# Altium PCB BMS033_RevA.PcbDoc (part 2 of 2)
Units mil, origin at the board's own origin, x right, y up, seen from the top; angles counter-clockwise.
Board outline 3000 x 3000 mil, 2 copper layers (Layer 1 - Top Layer, Layer 2 - Bottom Layer), stack 32 mil thick; 87 components, 36 nets, 183 pads, 163 vias.
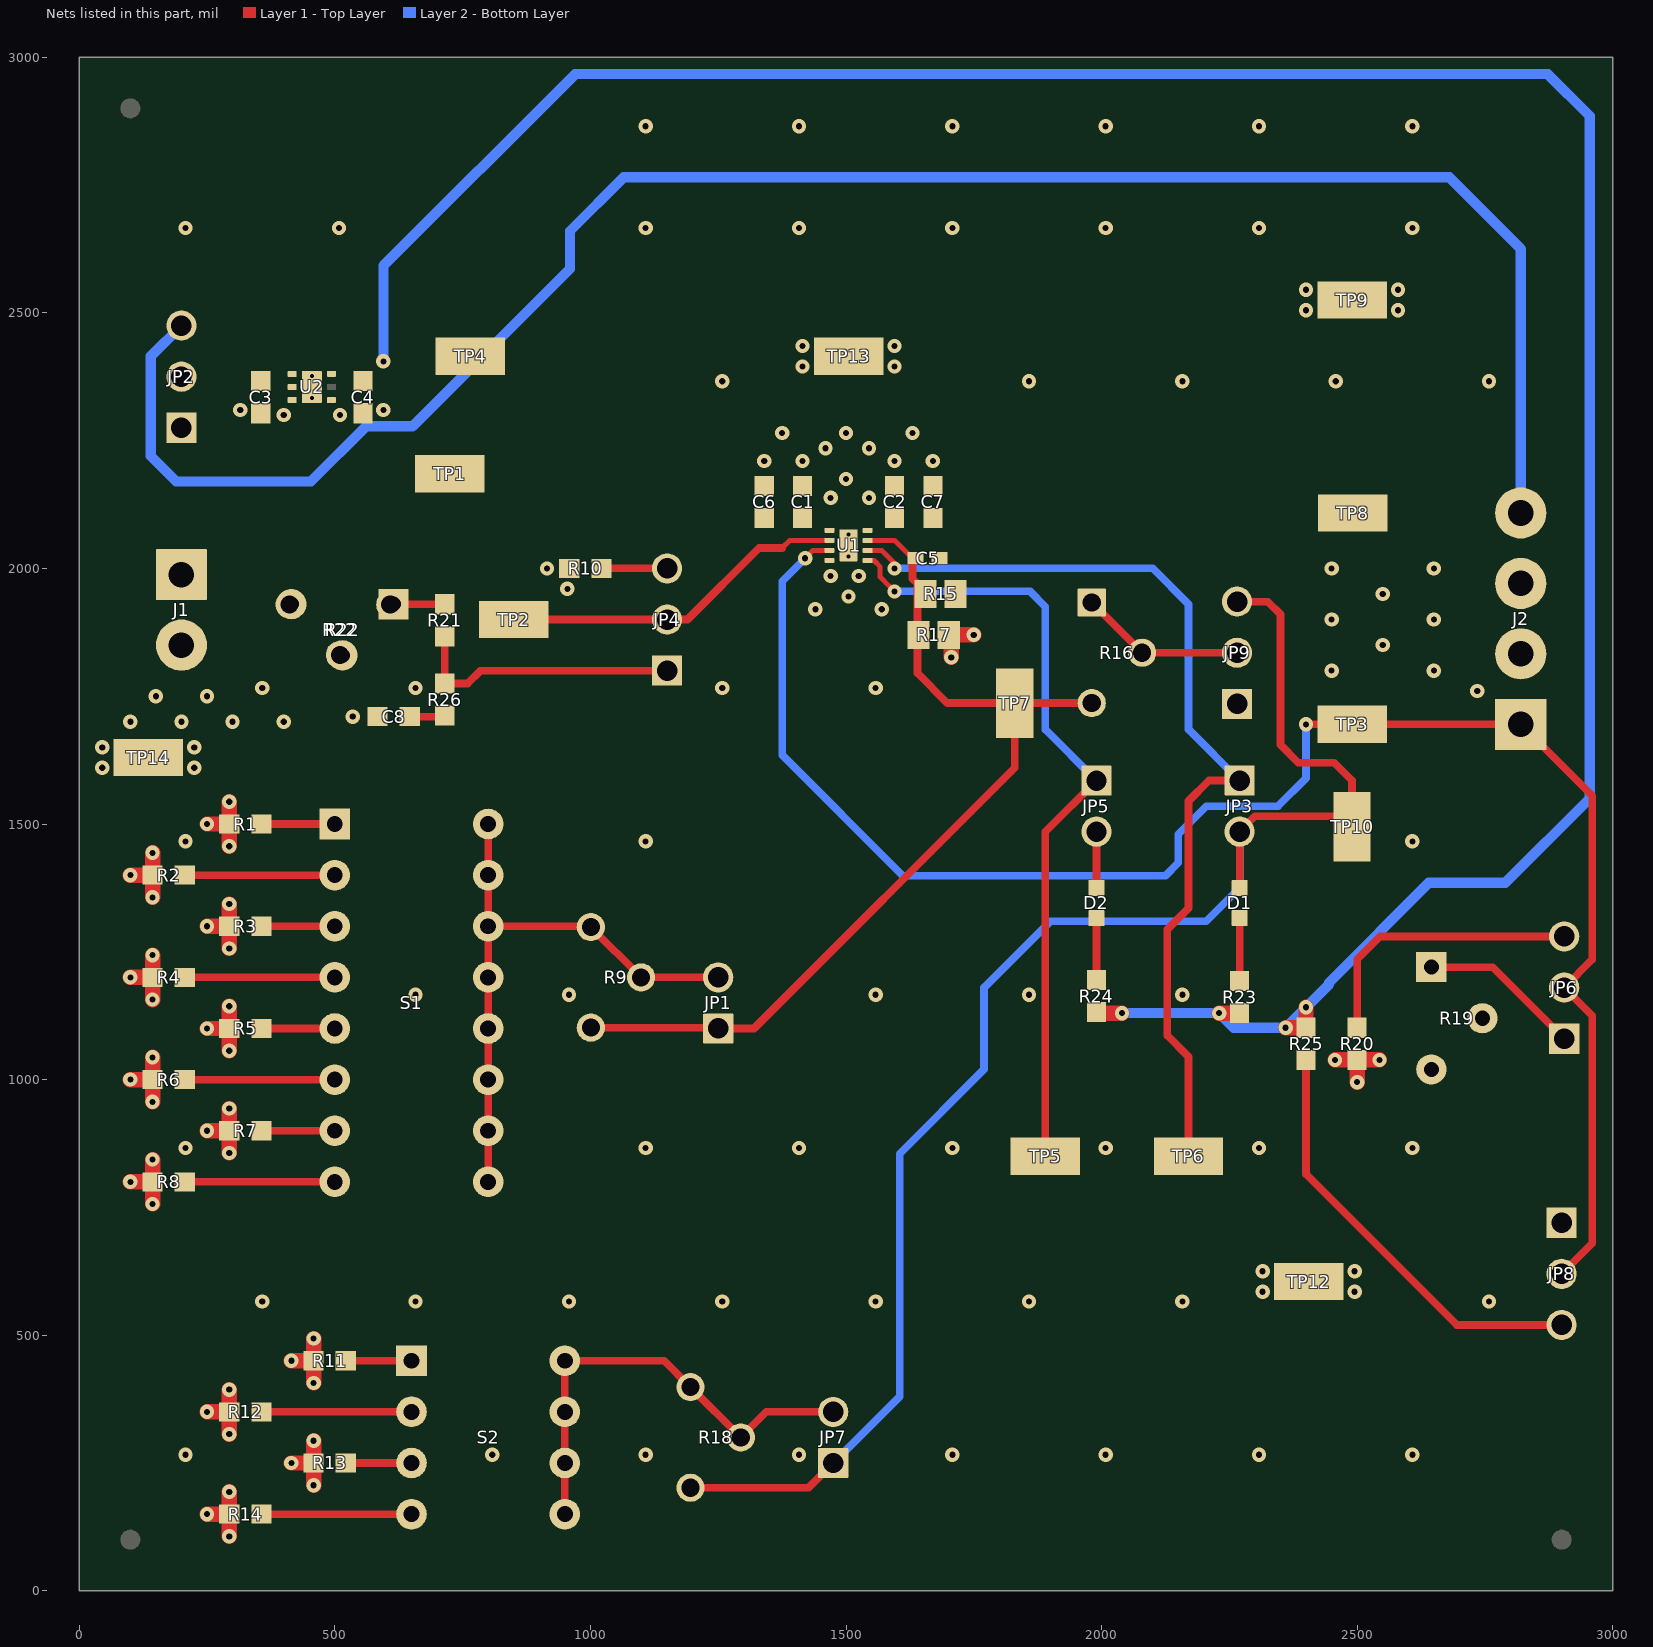
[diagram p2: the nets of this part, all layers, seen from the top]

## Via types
v1: diameter 28, hole 12, Layer 1 - Top Layer to Layer 2 - Bottom Layer, tented both sides, 159 vias
v2: diameter 19.68, hole 7.87, Layer 1 - Top Layer to Layer 2 - Bottom Layer, 4 vias

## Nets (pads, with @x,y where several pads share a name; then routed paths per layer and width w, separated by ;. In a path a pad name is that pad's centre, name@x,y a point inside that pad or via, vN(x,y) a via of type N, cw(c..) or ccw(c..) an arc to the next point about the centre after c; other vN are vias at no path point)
"/PG - TMR": D1.2 JP3.2 JP7.1 JP9.3 R18.3 TP10.1 | length 3002.3
  Layer 1 - Top Layer w15: R18.3@1195.79,201.57 1426.57,201.57 JP7.1@1475,250 ; JP9.3@2265,1935 2325,1935 2350,1910 2350,1655 2385,1620 2455,1620 2490,1585 TP10.1@2490,1495 2470,1515 2300,1515 JP3.2@2270,1485 D1.2@2270,1375
  Layer 2 - Bottom Layer w15: JP7.1@1475,250 1605,380 1605,855 1770,1020 1770,1180 1900,1310 2205,1310 2270,1375 JP3.2@2270,1485
Battery: C2.1 C5.1 C7.1 J2.4 JP2.3 R15.2 TP8.1 U1.8 | length 3845
  Layer 2 - Bottom Layer w20: JP2.3@200,2475 140,2415 140,2220 190,2170 453,2170 561.13,2278.13 652.1,2278.13 960,2586.03 960,2660 1065,2765 2680,2765 2820,2625 J2.4@2820,2108.39
GND: C1.2 C2.2 C3.2 C4.2 C6.2 C7.2 C8.1 J1.2 J2.2 J2.3 JP8.1 JP9.1 R1.1 R2.1 R3.1 R4.1 R5.1 R6.1 R7.1 R8.1 R10.2 R11.1 R12.1 R13.1 R14.1 R17.1 R19.2 R19.3 R20.1 R22.2 R22.3 TP9.1 TP12.1 TP13.1 TP14.1 U1.4 U1.9@1505,2045 U2.3 U2.4 U2.7@455,2355 | length 1790.7
  Layer 1 - Top Layer w30: v1(100,800) R8.1@143.5,800 ; v1(100,1000) R6.1@143.5,1000 ; v1(100,1200) R4.1@143.5,1200 ; v1(100,1400) R2.1@143.5,1400 ; v1(143.5,756.5) R8.1@143.5,800 ; v1(143.5,843.5) R8.1@143.5,800 ; v1(143.5,956.5) R6.1@143.5,1000 ; v1(143.5,1043.5) R6.1@143.5,1000 ; v1(143.5,1156.5) R4.1@143.5,1200 ; v1(143.5,1243.5) R4.1@143.5,1200 ; v1(143.5,1356.5) R2.1@143.5,1400 ; v1(143.5,1443.5) R2.1@143.5,1400 ; v1(250,150) R14.1@293.5,150 ; v1(250,350) R12.1@293.5,350 ; v1(250,900) R7.1@293.5,900 ; v1(250,1100) R5.1@293.5,1100 ; v1(250,1300) R3.1@293.5,1300 ; v1(250,1500) R1.1@293.5,1500 ; v1(293.5,106.5) R14.1@293.5,150 ; v1(293.5,193.5) R14.1@293.5,150 ; v1(293.5,306.5) R12.1@293.5,350 ; v1(293.5,393.5) R12.1@293.5,350 ; v1(293.5,856.5) R7.1@293.5,900 ; v1(293.5,943.5) R7.1@293.5,900 ; v1(293.5,1056.5) R5.1@293.5,1100 ; v1(293.5,1143.5) R5.1@293.5,1100 ; v1(293.5,1256.5) R3.1@293.5,1300 ; v1(293.5,1343.5) R3.1@293.5,1300 ; v1(293.5,1456.5) R1.1@293.5,1500 ; v1(293.5,1543.5) R1.1@293.5,1500 ; v1(415,250) R13.1@458.5,250 ; v1(415,450) R11.1@458.5,450 ; v1(458.5,206.5) R13.1@458.5,250 ; v1(458.5,293.5) R13.1@458.5,250 ; v1(458.5,406.5) R11.1@458.5,450 ; v1(458.5,493.5) R11.1@458.5,450 ; R17.1@1702.99,1870 v1(1750,1870) ; v1(1705.94,1825.94) R17.1@1705.94,1872.95 ; v1(2456.5,1038.5) R20.1@2500,1038.5 ; v1(2500,995) R20.1@2500,1038.5 ; v1(2543.5,1038.5) R20.1@2500,1038.5
  other v1: 208,266 808,266 1108,266 1408,266 1708,266 2008,266 2308,266 2608,266 358,566 658,566 958,566 1258,566 1558,566 1858,566 2158,566 2758,566 2315,585 2495,585 2315,625 2495,625 208,866 1108,866 1408,866 1708,866 2008,866 2308,866 2608,866 658,1166 958,1166 1558,1166 1858,1166 2158,1166 208,1466 1108,1466 2608,1466 45,1610 225,1610 45,1650 225,1650 100,1700 200,1700 300,1700 400,1700 535,1710 150,1750 250,1750 2735,1760 358,1766 658,1766 1258,1766 1558,1766 2450,1800 2650,1800 2550,1850 2450,1900 2650,1900 1440,1920 1570,1920 1505,1945 2550,1950 955,1960 1470,1985 1525,1985 915,2000 2450,2000 2650,2000 1470,2138 1545,2138 1500,2175 1340,2210 1415,2210 1595,2210 1670,2210 1460,2235 1545,2235 1375,2265 1500,2265 1630,2265 400,2300 510,2300 315,2310 595,2310 1258,2366 1858,2366 2158,2366 2458,2366 2758,2366 1415,2395 1595,2395 1415,2435 1595,2435 2400,2505 2580,2505 2400,2545 2580,2545 208,2666 508,2666 1108,2666 1408,2666 1708,2666 2008,2666 2308,2666 2608,2666 1108,2865 1408,2865 1708,2865 2008,2865 2308,2865 2608,2865
  other v2: 1505,2023.35 1505,2066.65 455,2333.35 455,2376.65
NetC1_1: C1.1 C6.1 J1.1 JP2.1 TP1.1 U1.1
NetC3_1: C3.1 JP2.2 U2.1 U2.2
NetC8_2: C8.2 R26.2 | length 69.3
  Layer 1 - Top Layer w15: C8.2@646.5,1710 712.99,1710 R26.2@715,1712.01
NetD1_1: D1.1 R23.1 | length 122.9
  Layer 1 - Top Layer w15: R23.1@2270,1193.03 D1.1@2270,1315.95
NetD2_1: D2.1 R24.1 | length 120.9
  Layer 1 - Top Layer w15: R24.1@1990,1195 D2.1@1990,1315.94
NetD2_2: D2.2 JP5.2 | length 132
  Layer 1 - Top Layer w15: D2.2@1990,1373.03 D2.2@1990,1375 JP5.2@1990,1485 JP5.2@1990,1505
NetJP1_2: JP1.2 R9.1 R9.2 S1.9 S1.10 S1.11 S1.12 S1.13 S1.14 S1.15 S1.16 | length 1191.4
  Layer 1 - Top Layer w15: S1.9@800,800 S1.10@800,900 S1.11@800,1000 S1.12@800,1100 S1.13@800,1200 S1.14@800,1300 ; S1.16@800,1500 S1.15@800,1400 S1.14@800,1300 ; JP1.2@1250,1200 R9.2@1099.21,1200 R9.1@1000.79,1298.43 999.21,1300 S1.14@800,1300
NetJP3_1: JP3.1 TP6.1 U1.6 | length 1909.3
  Layer 1 - Top Layer w10: U1.6@1542.4,2035.16 1569.84,2035.16 1595,2010 v1(1595,2000)
  Layer 1 - Top Layer w15: TP6.1@2170,850 2170,1045 2128.63,1086.37 2128.63,1293.63 2170,1335 2170,1545 2210,1585 JP3.1@2270,1585
  Layer 2 - Bottom Layer w15: v1(1595,2000) 2100,2000 2170,1930 2170,1685 JP3.1@2270,1585
NetJP4_1: JP4.1 R21.2 R26.1 | length 537.4
  Layer 1 - Top Layer w15: R21.2@715,1867.01 R26.1@715,1775 760,1775 785,1800 JP4.1@1150,1800
NetJP4_2: JP4.2 TP2.1 U1.2 | length 681.7
  Layer 1 - Top Layer w10: 1375,2040 1389.84,2054.84 U1.2@1467.6,2054.84
  Layer 1 - Top Layer w15: TP2.1@850,1900 JP4.2@1150,1900 1190,1900 1330,2040 1375,2040
NetJP4_3: JP4.3 R10.1 | length 128.5
  Layer 1 - Top Layer w15: R10.1@1021.5,2000 JP4.3@1150,2000
NetJP5_1: JP5.1 TP5.1 U1.5 | length 1568.8
  Layer 1 - Top Layer w10: U1.5@1542.4,2015.47 1554.53,2015.47 1566.87,2003.13 1566.87,1983.09 1584.74,1965.23 v1(1595,1955)
  Layer 1 - Top Layer w15: TP5.1@1890,850 1890,1485 JP5.1@1990,1585 JP5.1@2000,1595
  Layer 2 - Bottom Layer w15: v1(1595,1955) 1860,1955 1890,1925 1890,1685 JP5.1@1990,1585
NetJP6_1: JP6.1 R19.1 | length 318
  Layer 1 - Top Layer w15: R19.1@2645,1220 2765,1220 JP6.1@2905,1080
NetJP6_3: JP6.3 R20.2 | length 557.1
  Layer 1 - Top Layer w15: R20.2@2500,1101.5 2500,1235 2545,1280 JP6.3@2905,1280
NetJP7_2: JP7.2 R18.1 R18.2 S2.5 S2.6 S2.7 S2.8 | length 907.8
  Layer 1 - Top Layer w15: S2.5@950,150 S2.6@950,250 S2.7@950,350 S2.8@950,450 1144.21,450 R18.1@1195.79,398.43 R18.2@1294.21,300 1344.21,350 JP7.2@1475,350
NetJP8_3: JP8.3 R25.1 | length 845.7
  Layer 1 - Top Layer w15: R25.1@2400,1038.5 2400,815 2695,520 JP8.3@2900,520
NetJP9_2: JP9.2 R16.1 R16.2 | length 325
  Layer 1 - Top Layer w15: R16.1@1980.79,1933.43 R16.2@2079.21,1835 JP9.2@2265,1835
NetR1_2: R1.2 S1.1 | length 143.5
  Layer 1 - Top Layer w15: R1.2@356.5,1500 S1.1@500,1500
NetR2_2: R2.2 S1.2 | length 293.5
  Layer 1 - Top Layer w15: R2.2@206.5,1400 S1.2@500,1400
NetR3_2: R3.2 S1.3 | length 143.5
  Layer 1 - Top Layer w15: R3.2@356.5,1300 S1.3@500,1300
NetR4_2: R4.2 S1.4 | length 293.5
  Layer 1 - Top Layer w15: R4.2@206.5,1200 S1.4@500,1200
NetR5_2: R5.2 S1.5 | length 143.5
  Layer 1 - Top Layer w15: R5.2@356.5,1100 S1.5@500,1100
NetR6_2: R6.2 S1.6 | length 293.5
  Layer 1 - Top Layer w15: R6.2@206.5,1000 S1.6@500,1000
NetR7_2: R7.2 S1.7 | length 143.5
  Layer 1 - Top Layer w15: R7.2@356.5,900 S1.7@500,900
NetR8_2: R8.2 S1.8 | length 293.5
  Layer 1 - Top Layer w15: R8.2@206.5,800 S1.8@500,800
NetR11_2: R11.2 S2.1 | length 128.5
  Layer 1 - Top Layer w15: R11.2@521.5,450 S2.1@650,450
NetR12_2: R12.2 S2.2 | length 293.5
  Layer 1 - Top Layer w15: R12.2@356.5,350 S2.2@650,350
NetR13_2: R13.2 S2.3 | length 128.5
  Layer 1 - Top Layer w15: R13.2@521.5,250 S2.3@650,250
NetR14_2: R14.2 S2.4 | length 293.5
  Layer 1 - Top Layer w15: R14.2@356.5,150 S2.4@650,150
NetR21_1: R21.1 R22.1 | length 100
  Layer 1 - Top Layer w15: R22.1@615,1930 R21.1@715,1930
Pull-Up: C4.1 R23.2 R24.2 R25.2 TP4.1 U2.6 | length 5356.8
  Layer 1 - Top Layer w30: R24.2@1990,1132.01 1991.97,1130.04 v1(2040,1130.04) ; v1(2230,1130.04) R23.2@2270,1130.04 ; v1(2360,1101.5) R25.2@2400,1101.5 v1(2400,1141.5)
  Layer 2 - Bottom Layer w20: v1(595,2405) 595,2592 970,2967 2873,2967 2955,2885 2955,1550 2790,1385 2640,1385 2445,1190 2445,1186.5 v1(2400,1141.5) v1(2360,1101.5) 2258.54,1101.5 v1(2230,1130.04) v1(2040,1130.04)
"TS - /CE": J2.1 JP6.2 JP8.2 TP3.1 U1.3 | length 3420.6
  Layer 1 - Top Layer w10: v1(1420,2020) 1435.16,2035.16 U1.3@1467.6,2035.16
  Layer 1 - Top Layer w15: v1(2400,1695) TP3.1@2490,1695 J2.1@2820,1695 2960,1555 2960,1235 JP6.2@2905,1180 2960,1125 2960,680 JP8.2@2900,620
  Layer 2 - Bottom Layer w15: v1(1420,2020) 1375,1975 1375,1635 1611.03,1398.97 2125,1398.97 2150,1423.97 2150,1480 2205,1535 2345,1535 2400,1590 v1(2400,1695)
"VSET - FB": C5.2 JP1.1 R9.3 R15.1 R16.3 R17.2 TP7.1 U1.7 | length 1863.8
  Layer 1 - Top Layer w10: U1.7@1542.4,2054.84 1595.16,2054.84 C5.2@1630,2020
  Layer 1 - Top Layer w15: R9.3@1000.79,1101.57 1248.43,1101.57 JP1.1@1250,1100 1320,1100 1830,1610 TP7.1@1830,1736.57 ; C5.2@1630,2020 1630,1980 1640,1970 1640,1950 1640,1915 1640,1870 1640,1795 1698.43,1736.57 TP7.1@1830,1736.57 ; R16.3@1980.79,1736.57 TP7.1@1830,1736.57
pads on no net: FID1.1 FID2.1 FID3.1 H1.0 H2.0 H3.0 H4.0 LBL1.0 SH-JP1.0 SH-JP2.0 SH-JP3.0 SH-JP4.0 SH-JP5.0 SH-JP6.0 SH-JP7.0 SH-JP8.0 SH-JP9.0 U1.9@1505,2027.28 U1.9@1505,2062.72 U2.5 U2.7@455,2337.28 U2.7@455,2372.72

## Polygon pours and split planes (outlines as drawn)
GND on Layer 2 - Bottom Layer "Layer 2 - Bottom Layer - GND" (solid, remove dead copper, pour order 2): 20,20 2980,20 2980,2980 20,2980
GND on Layer 1 - Top Layer "Layer 1 - Top Layer - GND" (solid, remove dead copper, pour order 0): 20,20 2980,20 2980,2980 20,2980

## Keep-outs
Keep-Out Layer:
  text ".Layer_Name" at 577,-858.49 h60

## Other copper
Layer 1 - Top Layer:
  region net Battery: 1703.7,1910 1696.8,1916.9 1696.8,1978.2 1691.85,1983.15 1680,1995 1665,2010 1665,2035 1650,2050 1626,2050 1607,2069 1532,2069 1532,2082 1575,2125 1640,2125 1705,2125 1720,2140 1720,2190 1790,2260 1865,2260 2850,2260 2880,2230 2880,2080 2850,2050 1763,2050 1750,2037 1750,1918 1742,1910
  region net NetC1_1: 1440,2125 1310,2125 1295,2140 1295,2200 1235,2260 280,2260 230,2310 140,2310 100,2270 100,1970 140,1930 275,1930 414.5,2069.5 1476.5,2069.5 1478,2071 1478,2087
  region net NetC3_1: 421,2345 427,2351 427,2384 401,2410 175,2410 165,2400 165,2355 175,2345
  region net Pull-Up: 484,2375 486,2373 509,2373 536,2346 826,2346 845,2365 845,2450 825,2470 531,2470 484,2423
  region net GND: 1487,2105 1475.29,2116.71 1475.29,2135 1522.62,2135 1523,2009.99 1537.78,1995.22 1452.78,1995.22 1448.25,1999.75 1448.25,2016.25 1453,2021 1483,2021 1487,2025
  region net GND: 433,2336 435,2338 435,2427 451,2443 460,2443 462,2441 470.58,2441 475.48,2436.11 475.48,2342.52 479,2339 525,2339 533,2331 533,2322.17 405,2322 402,2325 402,2329 409,2336
  text ".Layer_Name" at 577,-858.49 h60
Layer 2 - Bottom Layer:
  pour cut-out: 1430.35,278.54 1430.35,349.74 1440,350 1440,278.54
  text ".Layer_Name" at 577,-858.49 h60

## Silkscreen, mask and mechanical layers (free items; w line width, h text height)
Top Overlay:
  lines w7: 272,2270 272,2305 ; 274,2356 274,2391 ; 277,2270 277,2305 ; 279,2356 279,2391 ; 282,2270 282,2305 ; 284,2356 284,2391 ; 287,2270 287,2305 ; 289,2356 289,2391 ; 291,2270 291,2305 ; 293,2356 293,2391 ; 297,2270 297,2305 ; 299,2356 299,2391 ; 1224,1881 1224,1916 ; 1224,1961 1224,1996 ; 1229,1881 1229,1916 ; 1229,1961 1229,1996 ; 1234,1881 1234,1916 ; 1234,1961 1234,1996 ; 1239,1881 1239,1916 ; 1239,1961 1239,1996 ; 1243,1881 1243,1916 ; 1243,1961 1243,1996 ; 1249,1881 1249,1916 ; 1249,1961 1249,1996 ; 1324,1081 1324,1116 ; 1324,1181 1324,1216 ; 1329,1081 1329,1116 ; 1329,1181 1329,1216 ; 1334,1081 1334,1116 ; 1334,1181 1334,1216 ; 1339,1081 1339,1116 ; 1339,1181 1339,1216 ; 1343,1081 1343,1116 ; 1343,1181 1343,1216 ; 1349,1081 1349,1116 ; 1349,1181 1349,1216 ; 1549,231 1549,266 ; 1549,331 1549,366 ; 1554,231 1554,266 ; 1554,331 1554,366 ; 1559,231 1559,266 ; 1559,331 1559,366 ; 1564,231 1564,266 ; 1564,331 1564,366 ; 1568,231 1568,266 ; 1568,331 1568,366 ; 1574,231 1574,266 ; 1574,331 1574,366 ; 1891,1469 1891,1504 ; 1891,1569 1891,1604 ; 1897,1469 1897,1504 ; 1897,1569 1897,1604 ; 1901,1469 1901,1504 ; 1901,1569 1901,1604 ; 1906,1469 1906,1504 ; 1906,1569 1906,1604 ; 1911,1469 1911,1504 ; 1911,1569 1911,1604 ; 1916,1469 1916,1504 ; 1916,1569 1916,1604 ; 2171,1469 2171,1504 ; 2171,1569 2171,1604 ; 2177,1469 2177,1504 ; 2177,1569 2177,1604 ; 2181,1469 2181,1504 ; 2181,1569 2181,1604 ; 2186,1469 2186,1504 ; 2186,1569 2186,1604 ; 2191,1469 2191,1504 ; 2191,1569 2191,1604 ; 2196,1469 2196,1504 ; 2196,1569 2196,1604 ; 2806,1164 2806,1199 ; 2806,1264 2806,1299 ; 2812,1164 2812,1199 ; 2812,1264 2812,1299 ; 2816,1164 2816,1199 ; 2816,1264 2816,1299 ; 2821,1164 2821,1199 ; 2821,1264 2821,1299 ; 2826,1164 2826,1199 ; 2826,1264 2826,1299 ; 2831,1164 2831,1199 ; 2831,1264 2831,1299 ; 267,2270 267,2305 302,2305 302,2270 267,2270 ; 269,2356 269,2391 304,2391 304,2356 269,2356 ; 1219,1881 1219,1916 1254,1916 1254,1881 1219,1881 ; 1219,1961 1254,1961 1254,1996 1219,1996 1219,1961 ; 1319,1081 1354,1081 1354,1116 1319,1116 1319,1081 ; 1319,1181 1354,1181 1354,1216 1319,1216 1319,1181 ; 1544,231 1579,231 1579,266 1544,266 1544,231 ; 1544,331 1579,331 1579,366 1544,366 1544,331 ; 1886,1469 1921,1469 1921,1504 1886,1504 1886,1469 ; 1886,1569 1921,1569 1921,1604 1886,1604 1886,1569 ; 2166,1469 2201,1469 2201,1504 2166,1504 2166,1469 ; 2166,1569 2201,1569 2201,1604 2166,1604 2166,1569 ; 2801,1164 2836,1164 2836,1199 2801,1199 2801,1164 ; 2801,1264 2836,1264 2836,1299 2801,1299 2801,1264
  text "OUT / (BAT)" at 109,2729 h70
  text "REG" at 139,2654 h70
  text "IN(+)" at 139,2554 h70
  text "OUT (Bat+)" at 2650,2435 h70
  text "GND" at 2420,2425 h75
  text "GND (Bat-)" at 2655,2364.18 h70
  text "GND" at 1435,2315 h75
  text "PULLUP" at 650,2310 h75
  text "GND" at 2750,2277.59 h70
  text "TS" at 2785,2203.39 h70
  text "/PG" at 2205,2144 h70
  text "VIN" at 670,2085 h75
  text "FB-GND" at 2143,2075 h70
  text "GND" at 2200,2008 h70
  text "BAT" at 2429,2005 h75
  text "ISET - ADJ" at 362,2003 h70
  text "FIXED" at 1266.56,1956.56 h70
  text "ISET" at 1265,1880 h70
  text "ISET" at 783,1805 h75
  text "ADJ" at 1215,1780 h70
  text "VSET-FB" at 1495,1685 h75
  text "TS-/CE" at 2385,1595 h75
  text "GND" at 65,1525 h75
  text "FIXED" at 2795,1490 h70
  text "TS" at 2863,1423.5 h70
  text "VSET-ADJ" at 903,1367 h70
  text "/PG-TMR" at 2418,1359 h75
  text "ADJ" at 2840,1353 h70
  text "STAT" at 1905,1235 h75
  text "PG" at 2230,1235 h75
  text "PG" at 2125,705 h75
  text "STAT" at 1805,690 h75
  text "GND" at 2335,500 h75
  text "TMR-ADJ" at 1105,470 h70
  text "ON" at 2854,402 h70
  text "/CE" at 2844,335.94 h70
  text "OFF" at 2838,270 h70
  text ".Layer_Name" at 577,-858.49 h60
Bottom Overlay:
  text ".Layer_Name" at 577,-858.49 h60
Top Paste:
  text ".Layer_Name" at 577,-858.49 h60
Bottom Paste:
  text ".Layer_Name" at 577,-858.49 h60
Top Solder:
  text ".Layer_Name" at 577,-858.49 h60
  text ".Layer_Name" at 577,-858.49 h60
Bottom Solder:
  text ".Layer_Name" at 577,-858.49 h60
Drill Guide:
  text ".Layer_Name" at 577,-858.49 h60
M1 Board Outline:
  the board outline again, w10
  text ".Layer_Name" at 577,-858.49 h60
M2 Board Dimensions:
  rectangle: 0,-275 125,-150
  rectangle: 125,-400 500,-275
  lines w7: 0,-275 1000,-275 ; 125,-400 125,-150 ; 250,-400 250,-150 ; 500,-400 500,-150 ; 750,-400 750,-150 ; 0,-400 1000,-400 1000,-150 0,-150 0,-400
  text ".Layer_Name" at 577,-858.49 h60
M3 3D STEP Top:
  text ".Layer_Name" at 577,-858.49 h60
M4 3D STEP Bottom:
  text ".Layer_Name" at 577,-858.49 h60
M5 Assembly Top:
  lines w10: -292,-930.17 6308,-930.17 ; -292,-726.83 6310,-726.83 ; -292,-523.5 -292,-1133.5 3713,-1133.5 6310,-1133.5 6310,-523.5 -291.5,-523.5 -291.5,-1133.5 1284,-1133.5 ; 2173,-1133.5 2173,-523.5 ; 3440,-726.83 3440,-523.5 ; 4280,-726.83 4280,-523.5 ; 4902,-1140 4902,-937.17
  text "COMPONENTS MARKED 'DNP' SHOULD NOT BE POPULATED." at 1153.5,-318.5 h60
  text "ASSEMBLY VARIANT:" at 1153,-434 h60
  text ".VariantName" at 2189,-434 h60
  text "PCB VIEWED FROM TOP SIDE" at -228.5,-655.67 h60
  text "BOARD #:" at 2248,-655.67 h60
  text ".PRJ_Number" at 2793.5,-655.67 h60
  text "REV:" at 3638,-655.67 h60
  text ".PCB_Rev" at 3929.5,-655.67 h60
  text "SVN REV:" at 4476,-655.67 h60
  text ".VersionControl_RevNumber" at 4982,-655.67 h60
  text "TID #:" at 2248,-859 h60
  text ".TID" at 2793.5,-859 h60
  text "PLOT NAME =" at -228.5,-1064.34 h60
  text ".plot_File_Name" at 577,-1064.34 h60
  text "GENERATED    :" at 2250,-1064.34 h60
  text ".Print_Date" at 3119.5,-1064.34 h60
  text ".Print_Time" at 3848.5,-1064.34 h60
  text "TEXAS INSTRUMENTS" at 5113,-1064.34 h60
M6 Assembly Bottom:
  lines w10: -292.5,-727.33 6309.5,-727.33 ; -290.5,-930.67 6309.5,-930.67 ; 1115.5,-1140.5 1115.5,-937.67 ; 1737.5,-727.33 1737.5,-524 ; 2577.5,-727.33 2577.5,-524 ; 3844.5,-1134 3844.5,-524 ; 4733.5,-1134 6309,-1134 6309,-524 -292.5,-524 -292.5,-1134 2304.5,-1134 6309.5,-1134 6309.5,-524
  text "COMPONENTS MARKED 'DNP' SHOULD NOT BE POPULATED." at 6102,-318 h60
  text ".VariantName" at 5058,-434 h60
  text "ASSEMBLY VARIANT:" at 6097,-434 h60
  text ".VersionControl_RevNumber" at 1035.5,-656.17 h60
  text "SVN REV:" at 1541.5,-656.17 h60
  text ".PCB_Rev" at 2088,-656.17 h60
  text "REV:" at 2379.5,-656.17 h60
  text ".PRJ_Number" at 3224,-656.17 h60
  text "BOARD #:" at 3769.5,-656.17 h60
  text "PCB VIEWED FROM BOTTOM SIDE" at 6246,-656.17 h60
  text ".TID" at 3224,-859.5 h60
  text "TID #:" at 3769.5,-859.5 h60
  text "TEXAS INSTRUMENTS" at 904.5,-1064.84 h60
  text ".Print_Time" at 2169,-1064.84 h60
  text ".Print_Date" at 2898,-1064.84 h60
  text "GENERATED    :" at 3767.5,-1064.84 h60
  text ".plot_File_Name" at 5440.5,-1064.84 h60
  text "PLOT NAME =" at 6246,-1064.84 h60
M9 Title Sheet:
  drawing of 1178 lines, arcs and shapes, not listed
  text "1" at 739.84,8036.5 h70
  text "2" at 3235.5,8036.5 h70
  text "3" at 5724.84,8036.5 h70
  text "4" at 8231.51,8036.5 h70
  text "5" at 10730.5,8036.5 h70
  text "6" at 13235.5,8036.5 h70
  text "A" at -416.5,6893.5 h70
  text "A" at 14383.5,6893.5 h70
  text "B" at -416.5,4513.5 h70
  text "B" at 14383.5,4513.5 h70
  text "C" at -416.5,2138.5 h70
  text "C" at 14383.5,2138.5 h70
  text "PROJECT TITLE:" at 11343.5,277.5 h45
  text ".PRJ_Title" at 11393.5,144.17 h70
  text "DESIGNED FOR:" at 11343.5,-23.5 h45
  text ".PRJ_Customer" at 11393.5,-163.5 h70
  text "D" at -416.5,-231.5 h70
  text "D" at 14383.5,-231.5 h70
  text "FILE NAME:" at 11343.5,-323.5 h45
  text ".PCB_File_Name_No_Path" at 11393.5,-443.5 h70
  text "Texas Instruments (TI) and/or its licensors do not warrant the accuracy or completeness of this specification" at 6374,-605.34 h45
  text "ENGINEER:" at 11343.5,-613.5 h45
  text "LAYOUT BY:" at 12848.5,-613.5 h45
  text "or any information contained therein. TI and/or its licensors do not warrant that this design will meet" at 6329.01,-718 h45
  text ".PRJ_Engineer" at 11393.5,-768.49 h70
  text "JMM" at 12852,-800 h100
  text "s  o  l  u  t  i  o  n  s" at 13710,-803 h68
  text "the specifications, will be suitable for your application or fit for any particular purpose, or will operate in" at 6329.01,-830.67 h45
  text ".Layer_Name" at 577,-858.49 h60
  text "ALTIUM DESIGNER VERSION:" at 12848.5,-923.5 h45
  text "an implementation. TI and/or its licensors do not warrant that the design is production worthy. You should" at 6329.01,-943.33 h45
  text "completely validate and test your design implementation to confirm the system functionality for your application." at 6374,-1056 h45
  text ".print_Scale" at 11393.5,-1056.83 h70
  text ".Application_BuildNumber" at 12899,-1056.83 h70
  text "1" at 739.84,-1263.5 h70
  text "2" at 3235.5,-1263.5 h70
  text "3" at 5724.84,-1263.5 h70
  text "4" at 8231.51,-1263.5 h70
  text "5" at 10730.5,-1263.5 h70
  text "6" at 13235.5,-1263.5 h70
M10 Fab Notes:
  drawing of 189 lines, arcs and shapes, not listed
  text "DESIGN INFORMATION" at 12382.02,6356.17 h60
  text "MIN. TRACK WIDTH:" at 11737.46,6224.05 h60
  text "8" at 12833.7,6224.05 h60
  text "MIL" at 12988.46,6224.05 h60
  text "MIN. CLEARANCE:" at 11737.46,6099.92 h60
  text "0.2" at 12773.7,6099.93 h60
  text "mm" at 12988.46,6099.92 h60
  text "MIN. VIA PAD SIZE:" at 11737.46,5975.8 h60
  text "MIL" at 12988.46,5975.8 h60
  text "7.87" at 12625,5975 h60
  text "0.05mm (2MIL)" at 12432.46,5845.9 h60
  text "MINIMUM ANNULAR RING" at 11408.23,5837.67 h60
  text "EXTERNAL" at 13140.46,5837.67 h60
  text "PER" at 11608.23,5727.55 h60
  text "IPC-D-275 CLASS 2 LEVEL C" at 11828.23,5727.54 h60
  text "MIL, HOLES" at 13316.46,5627.07 h60
  text "+/-" at 12924,5618.48 h60
  text "+/-" at 13778,5618.48 h60
  text "REGISTRATION TOLERANCES:" at 11408.23,5617.42 h60
  text "METAL" at 12608,5617.42 h60
  text "5" at 13184.2,5617.42 h60
  text "3" at 14017.2,5617.42 h60
  text "MIL" at 14133.46,5617.42 h60
  text "HOLE SIZE TOLERANCE (UNLESS OTHERWISE SPECIFIED):" at 11408.23,5519.1 h60
  text "+/-" at 13778,5516.23 h60
  text "3" at 14017.2,5515.17 h60
  text "MIL" at 14133.46,5515.17 h60
  text "MATERIAL:" at 11333.46,5377.52 h60
  text "FR-4 High Tg" at 12319.9,5249 h60
  text "X" at 12175.46,5241.01 h60
  text "FR-408" at 11754.46,5236.49 h60
  text "OTHER" at 13242.46,5236.49 h60
  text "62 MIL (1.6mm) +/-10%" at 12074.56,5093.46 h60
  text "X" at 13245,5090 h60
  text "32 MIL" at 13805,5090 h60
  text "THICKNESS:" at 11408.23,5085.24 h60
  text "OTHER" at 13359.46,5085.24 h60
  text "TOLERANCE:" at 11408.23,4946.92 h60
  text "X" at 12256.46,4946.92 h60
  text "ANSI IPC-6012 TYPE 3 CLASS 2" at 12434.48,4946.92 h60
  text "OTHER +/-" at 12434.46,4802.73 h60
  text "BOW & TWIST:" at 11408.23,4657.54 h60
  text "X" at 12256.46,4657.54 h60
  text "ANSI IPC-6012 TYPE 3 CLASS 2" at 12434.48,4657.54 h60
  text "OTHER +/-" at 12434.46,4510.85 h60
  text "DRILLING:" at 11333.46,4380.23 h60
  text "NC_DRILL FILES" at 13094.46,4275.04 h60
  text "REFERENCE:" at 11408.23,4271.1 h60
  text "X" at 12065.46,4271.01 h60
  text "AS SHOWN" at 12243.46,4271.1 h60
  text "X" at 12966.46,4271.1 h60
  text "OTHER" at 13392.46,4128.85 h60
  text "PTH COPPER THICKNESS:" at 11407.91,4125.32 h60
  text "X" at 12547.14,4125.32 h60
  text "20-30 um" at 12675.14,4125.32 h60
  text "BOARD FINISH:" at 11333.46,3977.73 h60
  text "SILKSCREEN:" at 11488.68,3867.6 h60
  text "X" at 12446.46,3867.6 h60
  text "TOP" at 12563.46,3867.6 h60
  text "X" at 12956.46,3867.6 h60
  text "BOTTOM" at 13074.46,3867.6 h60
  text "SILKSCREEN COLOR:" at 11488.68,3712.41 h60
  text "X" at 12445.46,3712.41 h60
  text "WHITE" at 12563.46,3712.41 h60
  text "OTHER" at 13074.46,3712.41 h60
  text "X" at 12576.46,3568.96 h60
  text "GREEN" at 12694.46,3568.96 h60
  text "OTHER" at 13312.46,3568.96 h60
  text "SOLDER RESIST COLOR:" at 11488.68,3562.1 h60
  text "X" at 12576.46,3414.71 h60
  text "MATTE" at 12694.46,3414.71 h60
  text "SEMI-GLOSS" at 13312,3414.07 h60
  text "IMMERSION GOLD (ENIG)" at 12394.46,3241.94 h60
  text "ENEPIG" at 13732,3234.72 h60
  text "SURFACE FINISH:" at 11333.46,3233.72 h60
  text "X" at 12216.46,3233.72 h60
  text "IMM. TIN/SILVER OR EQUIV" at 11663,3096.4 h60
  text "OTHER" at 13094.46,3092.47 h60
  text "ARRAY/PANEL:" at 11333.46,2937.09 h60
  text "CUT AND TRIM PER M1 BOARD OUTLINE" at 12394.46,2928.87 h60
  text "N.C. ROUTE" at 12394.46,2792.9 h60
  text "X" at 13082.46,2792.9 h60
  text "V. SCORE" at 13260.46,2792.9 h60
  text "CERTIFICATION:" at 11333.46,2663.77 h60
  text "MATERIALS AND WORKMANSHIP FOR ALL PCBS" at 12058.46,2663.77 h60
  text "TO MEET OR EXCEED THE REQUIREMENTS OF:" at 12058.46,2569.71 h60
  text "X" at 11695.97,2441.08 h60
  text "ANSI IPC-A-600F CLASS ->" at 11823.96,2441.08 h60
  text "X" at 13471.97,2441.08 h60
  text "2" at 13581.96,2441.08 h60
  text "1" at 13266.96,2439.58 h60
  text "3" at 13935.96,2439.58 h60
  text "X" at 12507.97,2293.39 h60
  text "RoHS" at 12635.96,2293.39 h60
  text "OTHER" at 13280.36,2293.39 h60
  text "PER ORDER" at 13677.42,2293.39 h60
  text "ALL BOARDS MUST MEET OR EXCEED UL94-V0 REQUIREMENTS." at 11361,2139.57 h60
  text "PCB MUST BEAR THE UL94V-0 UL REGISTERED MATERIAL ID NUMBER" at 11361,2023.5 h60
  text "ADDITIONAL REQUIREMENTS:" at 11333.46,1854.08 h60
  text "MICROSECTION:" at 11408.23,1746.95 h60
  text "YES" at 12313.96,1746.95 h60
  text "REQUIRED" at 13175.46,1602.62 h60
  text "BARE BOARD ELEC. TEST:" at 11408.23,1599.76 h60
  text "NONE" at 12713.96,1599.76 h60
  text "X" at 13057.46,1599.76 h60
  text "PER ORDER" at 13767.46,1599.76 h60
  text "XX MIL VIAS REQUIRE NON-CONDUCTIVE FILL AND PLANARIZE" at 11576.38,1394.82 h59
  text "XX MIL VIAS REQUIRE CONDUCTIVE FILL AND PLANARIZE" at 11584.38,1290.84 h60
  text "OUTER XX MIL VIAS REQUIRE 50 OHM SINGLE-ENDED IMPEDANCE" at 11583.39,1127.46 h58
  text "LAYER 2 & 3 (INNER LAYERS) XX MIL WIDE, XX MIL SPACE / TRACES REQUIRE 100 OHM DIFFERENTIAL IMPEDANCE" at 11575.39,891.74 h60
  text ".Layer_Name" at 577,-858.49 h60
M11 Gerber Information:
  lines w10: -292,-930.17 6308,-930.17 ; -292,-726.83 6310,-726.83 ; -292,-523.5 -292,-1133.5 3713,-1133.5 6310,-1133.5 6310,-523.5 -291.5,-523.5 -291.5,-1133.5 1284,-1133.5 ; 2173,-1133.5 2173,-523.5 ; 3440,-726.83 3440,-523.5 ; 4280,-726.83 4280,-523.5 ; 4902,-1140 4902,-937.17
  text "ALL ARTWORK VIEWED FROM TOP SIDE" at -228.5,-655.67 h60
  text "BOARD #:" at 2248,-655.67 h60
  text ".PRJ_Number" at 2793.5,-655.67 h60
  text "REV:" at 3638,-655.67 h60
  text ".PCB_Rev" at 3929.5,-655.67 h60
  text "SVN REV:" at 4476,-655.67 h60
  text ".VersionControl_RevNumber" at 4982,-655.67 h60
  text "LAYER NAME =" at -228.5,-858.49 h60
  text "TID #:" at 2248,-859 h60
  text ".TID" at 2793.5,-859 h60
  text "PLOT NAME =" at -228.5,-1064.34 h60
  text ".plot_File_Name" at 577,-1064.34 h60
  text "GENERATED    :" at 2250,-1064.34 h60
  text ".Print_Date" at 3119.5,-1064.34 h60
  text ".Print_Time" at 3848.5,-1064.34 h60
  text "TEXAS INSTRUMENTS" at 5113,-1064.34 h60
M12 Stackup:
  drawing of 191 lines, arcs and shapes, not listed
  text "Layer" at 9287.5,7812.5 h60
  text "Name" at 9697.41,7812.5 h60
  text "Material" at 11107,7812.5 h60
  text "Thickness" at 11966.77,7812.5 h60
  text "Constant" at 12616.6,7812.5 h60
  text "Board Layer Stack" at 13186.47,7812.5 h60
  text "Top Overlay" at 9697.41,7692.5 h60
  text "Top Solder" at 9697.41,7572.5 h60
  text "Solder Resist" at 11107,7572.5 h60
  text "0.40mil" at 11966.77,7572.5 h60
  text "3.5" at 12616.6,7572.5 h60
  text "1" at 9287.5,7452.5 h60
  text "Layer 1 - Top Layer" at 9697.41,7452.5 h60
  text "2.80mil" at 11966.77,7452.5 h60
  text "Dielectric 1" at 9697.41,7332.5 h60
  text "FR-4 High-TG" at 11107,7332.5 h60
  text "26.40mil" at 11966.77,7332.5 h60
  text "4.4" at 12616.6,7332.5 h60
  text "2" at 9287.5,7212.5 h60
  text "Layer 2 - Bottom Layer" at 9697.41,7212.5 h60
  text "2.80mil" at 11966.77,7212.5 h60
  text "Bottom Solder" at 9697.41,7092.5 h60
  text "Solder Resist" at 11107,7092.5 h60
  text "0.40mil" at 11966.77,7092.5 h60
  text "3.5" at 12616.6,7092.5 h60
  text "Bottom Overlay" at 9697.41,6972.5 h60
  text ".Layer_Name" at 577,-858.49 h60
M13 Component Bodies Top:
  text ".Layer_Name" at 577,-858.49 h60
M14 Component Bodies Bottom:
  text ".Layer_Name" at 577,-858.49 h60
M15 Courtyards Top:
  text ".Layer_Name" at 577,-858.49 h60
M16 Courtyards Bottom:
  text ".Layer_Name" at 577,-858.49 h60
Drill Drawing:
  circle w10: c3367.4,1723.33 r33.33
  lines w10: 3334.07,1106.67 3350.74,1106.67 3350.74,1090 3384.07,1090 3384.07,1106.67 3400.74,1106.67 3400.74,1140 3384.07,1140 3384.07,1156.67 3350.74,1156.67 3350.74,1140 3334.07,1140 3334.07,1106.67 ; 3334.07,1240 3400.74,1240 3400.74,1306.67 3334.07,1306.67 3334.07,1240 ; 3334.07,1406.67 3350.74,1406.67 3367.4,1390 3384.07,1406.67 3400.74,1406.67 3384.07,1423.33 3400.74,1440 3384.07,1440 3367.4,1456.67 3350.74,1440 3334.07,1440 3350.74,1423.33 3334.07,1406.67 ; 3334.07,1540 3367.4,1556.67 3400.74,1540 3384.07,1573.33 3400.74,1606.67 3367.4,1590 3334.07,1606.67 3350.74,1573.33 3334.07,1540 ; 3334.07,1873.33 3367.4,1840 3400.74,1873.33 3367.4,1906.67 3334.07,1873.33 ; 3334.07,2056.67 3400.74,2056.67 3367.4,1990 3334.07,2056.67 ; 3334.07,2140 3334.07,2156.67 3350.74,2173.33 3334.07,2190 3334.07,2206.67 3350.74,2206.67 3367.4,2190 3384.07,2206.67 3400.74,2206.67 3400.74,2190 3384.07,2173.33 3400.74,2156.67 3400.74,2140 3384.07,2140 3367.4,2156.67 3350.74,2140 3334.07,2140
  lines w15: 3274.28,1045 10824.17,1045 ; 3274.28,2245 10824.17,2245 ; 3825.16,895 3825.16,2395 ; 4415,895 4415,2395 ; 5514.68,895 5514.68,2395 ; 6020.56,895 6020.56,2395 ; 6754.36,895 6754.36,2395 ; 9443.52,895 9443.52,2395 ; 10033.37,895 10033.37,2395 ; 3274.28,895 10824.17,895 10824.17,2395 3274.28,2395 3274.28,895
  text "Symbol" at 3364.28,2290 h72
  text "Count" at 3870.16,2290 h72
  text "Hole Size" at 4460,2290 h72
  text "Plated" at 5559.68,2290 h72
  text "Hole Type" at 6065.56,2290 h72
  text "Drill Layer Pair" at 6799.36,2290 h72
  text "Via/Pad" at 9488.52,2290 h72
  text "Pad Shape" at 10078.37,2290 h72
  text "4" at 3870.16,2140 h60
  text "7.87mil (0.200mm)" at 4460,2140 h60
  text "PTH" at 5559.68,2140 h60
  text "Round" at 6065.56,2140 h60
  text "Layer 1 - Top Layer - Layer 2 - Bottom Layer" at 6799.36,2140 h60
  text "Via" at 9488.52,2140 h60
  text "Rounded" at 10078.37,2140 h60
  text "159" at 3870.16,1990 h60
  text "12.00mil (0.305mm)" at 4460,1990 h60
  text "PTH" at 5559.68,1990 h60
  text "Round" at 6065.56,1990 h60
  text "Layer 1 - Top Layer - Layer 2 - Bottom Layer" at 6799.36,1990 h60
  text "Via" at 9488.52,1990 h60
  text "Rounded" at 10078.37,1990 h60
  text "6" at 3870.16,1840 h60
  text "29.53mil (0.750mm)" at 4460,1840 h60
  text "PTH" at 5559.68,1840 h60
  text "Round" at 6065.56,1840 h60
  text "Layer 1 - Top Layer - Layer 2 - Bottom Layer" at 6799.36,1840 h60
  text "Pad" at 9488.52,1840 h60
  text "(Mixed)" at 10078.37,1840 h60
  text "24" at 3870.16,1690 h60
  text "31.00mil (0.787mm)" at 4460,1690 h60
  text "PTH" at 5559.68,1690 h60
  text "Round" at 6065.56,1690 h60
  text "Layer 1 - Top Layer - Layer 2 - Bottom Layer" at 6799.36,1690 h60
  text "Pad" at 9488.52,1690 h60
  text "(Mixed)" at 10078.37,1690 h60
  text "3" at 3870.16,1540 h60
  text "35.43mil (0.900mm)" at 4460,1540 h60
  text "PTH" at 5559.68,1540 h60
  text "Round" at 6065.56,1540 h60
  text "Layer 1 - Top Layer - Layer 2 - Bottom Layer" at 6799.36,1540 h60
  text "Pad" at 9488.52,1540 h60
  text "(Mixed)" at 10078.37,1540 h60
  text "6" at 3870.16,1390 h60
  text "35.43mil (0.900mm)" at 4460,1390 h60
  text "PTH" at 5559.68,1390 h60
  text "Round" at 6065.56,1390 h60
  text "Layer 1 - Top Layer - Layer 2 - Bottom Layer" at 6799.36,1390 h60
  text "Pad" at 9488.52,1390 h60
  text "Rounded" at 10078.37,1390 h60
  text "23" at 3870.16,1240 h60
  text "40.00mil (1.016mm)" at 4460,1240 h60
  text "PTH" at 5559.68,1240 h60
  text "Round" at 6065.56,1240 h60
  text "Layer 1 - Top Layer - Layer 2 - Bottom Layer" at 6799.36,1240 h60
  text "Pad" at 9488.52,1240 h60
  text "(Mixed)" at 10078.37,1240 h60
  text "6" at 3870.16,1090 h60
  text "50.00mil (1.270mm)" at 4460,1090 h60
  text "PTH" at 5559.68,1090 h60
  text "Round" at 6065.56,1090 h60
  text "Layer 1 - Top Layer - Layer 2 - Bottom Layer" at 6799.36,1090 h60
  text "Pad" at 9488.52,1090 h60
  text "(Mixed)" at 10078.37,1090 h60
  text "231 Total" at 3870.16,940 h60
  text ".Layer_Name" at 577,-858.49 h60
M17 Embedded Cavity:
  text ".Layer_Name" at 577,-858.49 h60
M18 Embedded Assembly:
  text ".Layer_Name" at 577,-858.49 h60
M19 Embedded Keepout:
  text ".Layer_Name" at 577,-858.49 h60

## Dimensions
0,-400 to 1000,-400 on M2 Board Dimensions
0,0 to 0,3000 on M2 Board Dimensions
0,0 to 3000,0 on M2 Board Dimensions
